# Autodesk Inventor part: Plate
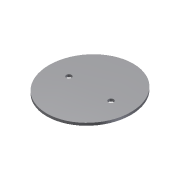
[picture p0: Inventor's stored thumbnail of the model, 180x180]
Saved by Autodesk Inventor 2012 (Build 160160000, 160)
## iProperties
Created: 2009-04
Part Number: Plate
Document SubType Name: Modeling
Designer: Sham
Density: 1 g/cm^3
Material: Default
Author: Sham
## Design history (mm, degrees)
sketch "Sketch1"
  geometry: C1 r 6.25 at (-50, 0); C2 r 6.25 at (50, 0); 4 further points; 1 other entity
  constraints: 2 centre point, 1 coincident, 5 other
  dimensions: "d1" = 12.5 diameter of C1; "d2" = 12.5 diameter of C2; "d3" = 100 distance of C2.centre C1.centre; "d4" = 102.5 distance of point (0, 0) point (0, 102.5); "d5" = 96.9 distance of point (0, 0) point (-96.9, 0); "d6" = 50 distance of point (0, 0) C1.centre
extrude "Extrusion1" new body sketch "Sketch1" distance "d7" = 6; taper "d8" = 0 deg
body "Solid1"
